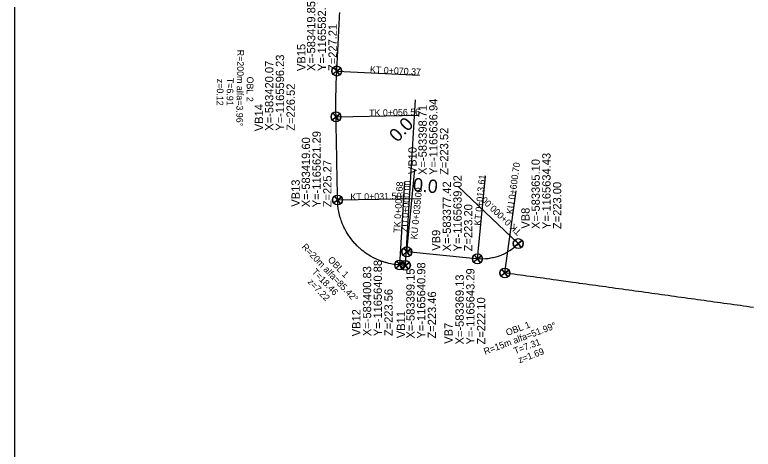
# Model space of a CAD drawing. Extents: x -583517 to -548566, y -1166112 to -1101582.
# Drawn here: x -583517 to -583294.2, y -1165696.4 to -1165565.5 of the extents above; entities that cross this region are included whole.
import ezdxf

# ---------------------------------------------------------------- set-up
doc = ezdxf.new("R2010")
doc.units = 0
for name, color, linetype in [('13', 7, 'Continuous'), ('56', 7, 'Continuous'), ('59', 7, 'Continuous'), ('8', 7, 'Continuous'), ('Body pricny rez', 7, 'Continuous'), ('Popis pricneho profilu', 7, 'Continuous')]:
    doc.layers.add(name, color=color, linetype=linetype)

msp = doc.modelspace()

# ---------------------------------------------------------------- linework, layer by layer
at = {"layer": '13'}
for points in [[(-583419.85, -1165582.42), (-583394.88, -1165583.68)], [(-583399.15, -1165640.98), (-583396.09, -1165591.07)], [(-583420.07, -1165596.23), (-583395.07, -1165595.77)], [(-583398.71, -1165636.94), (-583396.28, -1165612.06)], [(-583377.42, -1165639.02), (-583374.99, -1165614.13)], [(-583400.83, -1165640.88), (-583399.3, -1165615.92)], [(-583399.15, -1165640.98), (-583397.62, -1165616.03)], [(-583365.1, -1165634.43), (-583383.21, -1165617.19)], [(-583369.13, -1165643.29), (-583365.69, -1165618.53)], [(-583419.6, -1165621.29), (-583394.6, -1165620.82)]]:
    msp.add_lwpolyline(points, dxfattribs=at)
at = {"layer": '56'}
msp.add_lwpolyline([(-583365.1, -1165634.43), (-583365.66, -1165634.99), (-583365.81, -1165635.13), (-583366.26, -1165635.53), (-583366.57, -1165635.78), (-583366.88, -1165636.03), (-583367.37, -1165636.38), (-583367.53, -1165636.5), (-583368.21, -1165636.93), (-583368.21, -1165636.93), (-583368.9, -1165637.32), (-583369.08, -1165637.41), (-583369.62, -1165637.68), (-583369.98, -1165637.84), (-583370.36, -1165638), (-583370.91, -1165638.21), (-583371.11, -1165638.28), (-583371.86, -1165638.52), (-583371.87, -1165638.52), (-583372.65, -1165638.72), (-583372.83, -1165638.76), (-583373.43, -1165638.87), (-583373.82, -1165638.93), (-583374.22, -1165638.99), (-583374.81, -1165639.04), (-583375.02, -1165639.06), (-583375.81, -1165639.09), (-583375.82, -1165639.09), (-583376.62, -1165639.07), (-583376.81, -1165639.06), (-583377.42, -1165639.02), (-583377.81, -1165638.98), (-583378.8, -1165638.88), (-583379.8, -1165638.78), (-583380.79, -1165638.69), (-583381.79, -1165638.59), (-583382.78, -1165638.49), (-583383.78, -1165638.4), (-583384.77, -1165638.3), (-583385.77, -1165638.2), (-583386.76, -1165638.1), (-583387.76, -1165638.01), (-583388.75, -1165637.91), (-583389.75, -1165637.81), (-583390.74, -1165637.72), (-583391.74, -1165637.62), (-583392.74, -1165637.52), (-583393.73, -1165637.42), (-583394.73, -1165637.33), (-583395.72, -1165637.23), (-583396.72, -1165637.13), (-583397.71, -1165637.04), (-583398.71, -1165636.94)], dxfattribs=at)
at = {"layer": '8'}
for p, q in [((-583421.05, -1165583.31), (-583418.64, -1165581.52)), ((-583419.85, -1165582.42), (-583420.74, -1165581.21)), ((-583418.95, -1165583.62), (-583420.74, -1165581.22)), ((-583418.64, -1165581.52), (-583419.85, -1165582.42)), ((-583418.64, -1165581.52), (-583419.85, -1165582.42)), ((-583421.05, -1165583.31), (-583419.85, -1165582.42)), ((-583419.85, -1165582.42), (-583418.95, -1165583.62)), ((-583419.85, -1165582.42), (-583418.95, -1165583.62)), ((-583419.17, -1165597.43), (-583420.96, -1165595.03)), ((-583420.07, -1165596.23), (-583420.96, -1165595.03)), ((-583421.27, -1165597.13), (-583418.86, -1165595.34)), ((-583421.27, -1165597.13), (-583420.07, -1165596.23)), ((-583418.86, -1165595.34), (-583420.07, -1165596.23)), ((-583418.86, -1165595.34), (-583420.07, -1165596.23)), ((-583420.07, -1165596.23), (-583419.17, -1165597.44)), ((-583420.07, -1165596.23), (-583419.17, -1165597.44)), ((-583420.8, -1165622.18), (-583418.4, -1165620.39)), ((-583420.8, -1165622.18), (-583419.6, -1165621.29)), ((-583419.6, -1165621.29), (-583420.5, -1165620.08)), ((-583418.71, -1165622.49), (-583420.49, -1165620.08)), ((-583418.4, -1165620.39), (-583419.6, -1165621.29)), ((-583418.4, -1165620.39), (-583419.6, -1165621.29)), ((-583419.6, -1165621.29), (-583418.7, -1165622.49)), ((-583419.6, -1165621.29), (-583418.7, -1165622.49)), ((-583366.3, -1165635.32), (-583363.89, -1165633.53)), ((-583366.3, -1165635.32), (-583365.1, -1165634.43)), ((-583364.2, -1165635.63), (-583365.99, -1165633.22)), ((-583365.1, -1165634.43), (-583365.99, -1165633.22)), ((-583363.89, -1165633.53), (-583365.1, -1165634.43)), ((-583363.89, -1165633.53), (-583365.1, -1165634.43)), ((-583365.1, -1165634.43), (-583364.2, -1165635.63)), ((-583365.1, -1165634.43), (-583364.2, -1165635.63)), ((-583399.91, -1165637.83), (-583397.5, -1165636.04)), ((-583399.91, -1165637.83), (-583398.71, -1165636.94)), ((-583397.81, -1165638.14), (-583399.6, -1165635.73)), ((-583398.71, -1165636.94), (-583399.6, -1165635.73)), ((-583397.5, -1165636.04), (-583398.71, -1165636.94)), ((-583397.5, -1165636.04), (-583398.71, -1165636.94)), ((-583398.71, -1165636.94), (-583397.81, -1165638.14)), ((-583398.71, -1165636.94), (-583397.81, -1165638.14)), ((-583378.62, -1165639.91), (-583376.22, -1165638.12)), ((-583378.62, -1165639.91), (-583377.42, -1165639.02)), ((-583376.52, -1165640.22), (-583378.31, -1165637.81)), ((-583377.42, -1165639.02), (-583378.31, -1165637.81)), ((-583376.21, -1165638.12), (-583377.42, -1165639.02)), ((-583376.21, -1165638.12), (-583377.42, -1165639.02)), ((-583377.42, -1165639.02), (-583376.52, -1165640.22)), ((-583377.42, -1165639.02), (-583376.52, -1165640.22)), ((-583402.03, -1165641.77), (-583399.62, -1165639.98)), ((-583402.03, -1165641.77), (-583400.83, -1165640.88)), ((-583399.93, -1165642.08), (-583401.72, -1165639.67)), ((-583400.83, -1165640.88), (-583401.72, -1165639.67)), ((-583399.62, -1165639.98), (-583400.83, -1165640.88)), ((-583399.62, -1165639.98), (-583400.83, -1165640.88)), ((-583400.83, -1165640.88), (-583399.93, -1165642.08)), ((-583400.83, -1165640.88), (-583399.93, -1165642.08)), ((-583400.36, -1165641.88), (-583397.95, -1165640.09)), ((-583400.36, -1165641.88), (-583399.15, -1165640.98)), ((-583398.26, -1165642.18), (-583400.05, -1165639.78)), ((-583399.15, -1165640.98), (-583400.05, -1165639.78)), ((-583397.95, -1165640.09), (-583399.15, -1165640.98)), ((-583397.95, -1165640.09), (-583399.15, -1165640.98)), ((-583399.15, -1165640.98), (-583398.26, -1165642.18)), ((-583399.15, -1165640.98), (-583398.26, -1165642.18)), ((-583370.33, -1165644.19), (-583367.92, -1165642.4)), ((-583370.33, -1165644.19), (-583369.13, -1165643.29)), ((-583368.23, -1165644.5), (-583370.02, -1165642.09)), ((-583369.13, -1165643.29), (-583370.02, -1165642.09)), ((-583367.92, -1165642.4), (-583369.13, -1165643.29)), ((-583367.92, -1165642.4), (-583369.13, -1165643.29)), ((-583369.13, -1165643.29), (-583368.23, -1165644.5)), ((-583369.13, -1165643.29), (-583368.23, -1165644.5))]:
    msp.add_line(p, q, dxfattribs=at)
for centre in [(-583419.85, -1165582.42), (-583420.07, -1165596.23), (-583419.6, -1165621.29), (-583365.1, -1165634.43), (-583398.71, -1165636.94), (-583400.83, -1165640.88), (-583399.15, -1165640.98), (-583377.42, -1165639.02), (-583369.13, -1165643.29)]:
    msp.add_circle(centre, 1.5, dxfattribs=at)
for centre, start, end in [((-583419.85, -1165582.42), 126.6271, 216.6271), ((-583419.85, -1165582.42), 306.6271, 36.6271), ((-583419.85, -1165582.42), 306.6271, 36.6271), ((-583420.07, -1165596.23), 126.6271, 216.6271), ((-583420.07, -1165596.23), 306.6271, 36.6271), ((-583420.07, -1165596.23), 306.6271, 36.6271), ((-583419.6, -1165621.29), 126.6271, 216.6271), ((-583419.6, -1165621.29), 306.6271, 36.6271), ((-583419.6, -1165621.29), 306.6271, 36.6271), ((-583365.1, -1165634.43), 126.6271, 216.6271), ((-583365.1, -1165634.43), 306.6271, 36.6271), ((-583365.1, -1165634.43), 306.6271, 36.6271), ((-583398.71, -1165636.94), 126.6271, 216.6271), ((-583398.71, -1165636.94), 306.6271, 36.6271), ((-583398.71, -1165636.94), 306.6271, 36.6271), ((-583377.42, -1165639.02), 126.6271, 216.6271), ((-583377.42, -1165639.02), 306.6271, 36.6271), ((-583377.42, -1165639.02), 306.6271, 36.6271), ((-583400.83, -1165640.88), 126.6271, 216.6271), ((-583399.15, -1165640.98), 126.6271, 216.6271), ((-583400.83, -1165640.88), 306.6271, 36.6271), ((-583400.83, -1165640.88), 306.6271, 36.6271), ((-583399.15, -1165640.98), 306.6271, 36.6271), ((-583399.15, -1165640.98), 306.6271, 36.6271), ((-583369.13, -1165643.29), 126.6271, 216.6271), ((-583369.13, -1165643.29), 306.6271, 36.6271), ((-583369.13, -1165643.29), 306.6271, 36.6271)]:
    msp.add_arc(centre, 1.5, start, end, dxfattribs=at)
at = {"layer": 'Body pricny rez'}
for points in [[(-583399.15, -1165640.98), (-583400.15, -1165640.92), (-583400.83, -1165640.88), (-583401.15, -1165640.86), (-583401.73, -1165640.8), (-583402.14, -1165640.75), (-583402.62, -1165640.69), (-583403.13, -1165640.6), (-583403.51, -1165640.53), (-583404.11, -1165640.4), (-583404.4, -1165640.33), (-583405.08, -1165640.15), (-583405.27, -1165640.1), (-583406.03, -1165639.85), (-583406.13, -1165639.82), (-583406.97, -1165639.51), (-583406.97, -1165639.51), (-583406.98, -1165639.51), (-583407.81, -1165639.15), (-583407.89, -1165639.12), (-583408.62, -1165638.77), (-583408.79, -1165638.68), (-583409.42, -1165638.34), (-583409.67, -1165638.2), (-583410.2, -1165637.88), (-583410.52, -1165637.67), (-583410.95, -1165637.38), (-583411.34, -1165637.11), (-583411.68, -1165636.85), (-583412.14, -1165636.5), (-583412.39, -1165636.29), (-583412.9, -1165635.85), (-583413.07, -1165635.7), (-583413.63, -1165635.17), (-583413.73, -1165635.08), (-583414.33, -1165634.45), (-583414.35, -1165634.42), (-583414.95, -1165633.74), (-583414.98, -1165633.7), (-583415.51, -1165633.04), (-583415.6, -1165632.91), (-583416.04, -1165632.31), (-583416.18, -1165632.1), (-583416.54, -1165631.55), (-583416.72, -1165631.26), (-583417, -1165630.78), (-583417.22, -1165630.39), (-583417.43, -1165629.98), (-583417.67, -1165629.5), (-583417.82, -1165629.17), (-583418.08, -1165628.58), (-583418.18, -1165628.33), (-583418.44, -1165627.65), (-583418.49, -1165627.49), (-583418.75, -1165626.7), (-583418.77, -1165626.63), (-583419.01, -1165625.76), (-583419.01, -1165625.74), (-583419.21, -1165624.88), (-583419.23, -1165624.76), (-583419.37, -1165623.99), (-583419.4, -1165623.77), (-583419.48, -1165623.09), (-583419.52, -1165622.78), (-583419.56, -1165622.19), (-583419.58, -1165621.78), (-583419.6, -1165621.29), (-583419.61, -1165620.78), (-583419.63, -1165619.78), (-583419.65, -1165618.78), (-583419.67, -1165617.78), (-583419.68, -1165616.78), (-583419.7, -1165615.78), (-583419.72, -1165614.78), (-583419.74, -1165613.78), (-583419.76, -1165612.79), (-583419.78, -1165611.79), (-583419.8, -1165610.79), (-583419.81, -1165609.79), (-583419.83, -1165608.79), (-583419.85, -1165607.79), (-583419.87, -1165606.79), (-583419.89, -1165605.79), (-583419.91, -1165604.79), (-583419.93, -1165603.79), (-583419.94, -1165602.79), (-583419.96, -1165601.79), (-583419.98, -1165600.79), (-583420, -1165599.79), (-583420.02, -1165598.79), (-583420.04, -1165597.79), (-583420.06, -1165596.79), (-583420.07, -1165596.23), (-583420.07, -1165595.79), (-583420.09, -1165594.79), (-583420.1, -1165593.79), (-583420.1, -1165592.79), (-583420.1, -1165592.78), (-583420.1, -1165591.79), (-583420.09, -1165590.79), (-583420.08, -1165589.79), (-583420.08, -1165589.32), (-583420.07, -1165588.79), (-583420.05, -1165587.79), (-583420.02, -1165586.79), (-583419.99, -1165585.87), (-583419.99, -1165585.79), (-583419.95, -1165584.79), (-583419.91, -1165583.79), (-583419.87, -1165582.79), (-583419.85, -1165582.42), (-583419.82, -1165581.79), (-583419.76, -1165580.79), (-583419.71, -1165579.8), (-583419.66, -1165578.8), (-583419.61, -1165577.8), (-583419.56, -1165576.8), (-583419.51, -1165575.8), (-583419.46, -1165574.8), (-583419.41, -1165573.8), (-583419.36, -1165572.8), (-583419.31, -1165571.81), (-583419.26, -1165570.81), (-583419.21, -1165569.81), (-583419.16, -1165568.81), (-583419.11, -1165567.81), (-583419.06, -1165566.81), (-583419.01, -1165565.81), (-583418.96, -1165564.81)], [(-583294.14, -1165653.69), (-583295.13, -1165653.55), (-583296.12, -1165653.42), (-583297.11, -1165653.28), (-583298.1, -1165653.14), (-583299.1, -1165653.01), (-583300.09, -1165652.87), (-583301.08, -1165652.73), (-583302.07, -1165652.59), (-583303.06, -1165652.46), (-583304.05, -1165652.32), (-583305.04, -1165652.18), (-583306.03, -1165652.04), (-583307.02, -1165651.91), (-583308.01, -1165651.77), (-583309, -1165651.63), (-583309.99, -1165651.49), (-583310.98, -1165651.36), (-583311.97, -1165651.22), (-583312.96, -1165651.08), (-583313.95, -1165650.94), (-583314.94, -1165650.81), (-583315.93, -1165650.67), (-583316.92, -1165650.53), (-583317.92, -1165650.4), (-583318.91, -1165650.26), (-583319.9, -1165650.12), (-583320.89, -1165649.98), (-583321.88, -1165649.85), (-583322.87, -1165649.71), (-583323.86, -1165649.57), (-583324.85, -1165649.43), (-583325.84, -1165649.3), (-583326.83, -1165649.16), (-583327.82, -1165649.02), (-583328.81, -1165648.88), (-583329.8, -1165648.75), (-583330.79, -1165648.61), (-583331.78, -1165648.47), (-583332.77, -1165648.34), (-583333.76, -1165648.2), (-583334.75, -1165648.06), (-583335.74, -1165647.92), (-583336.74, -1165647.79), (-583337.73, -1165647.65), (-583338.72, -1165647.51), (-583339.71, -1165647.37), (-583340.7, -1165647.24), (-583341.69, -1165647.1), (-583342.68, -1165646.96), (-583343.67, -1165646.82), (-583344.66, -1165646.69), (-583345.65, -1165646.55), (-583346.64, -1165646.41), (-583346.88, -1165646.38), (-583347.63, -1165646.27), (-583348.62, -1165646.14), (-583353.57, -1165645.45), (-583354.56, -1165645.31), (-583355.56, -1165645.18), (-583356.55, -1165645.04), (-583357.54, -1165644.9), (-583358.53, -1165644.76), (-583359.52, -1165644.63), (-583360.51, -1165644.49), (-583361.5, -1165644.35), (-583362.49, -1165644.21), (-583363.48, -1165644.08), (-583364.47, -1165643.94), (-583365.46, -1165643.8), (-583366.45, -1165643.66), (-583367.44, -1165643.53), (-583368.43, -1165643.39), (-583369.13, -1165643.29)]]:
    msp.add_lwpolyline(points, dxfattribs=at)
at = {"layer": 'Popis pricneho profilu'}
msp.add_lwpolyline([(-583516.97, -1166111.82), (-583516.97, -1165166.82), (-583071.47, -1165166.82), (-583071.47, -1166111.82)], close=True, dxfattribs=at)

# ---------------------------------------------------------------- texts
at = {"layer": '13'}
for s, height, rotation, p in [('R=200m alfa=3.96%%d', 2, 269.0882, (-583449.81, -1165575.97)), ('KT 0+070.37', 2, 357.1091, (-583409.86, -1165582.92)), ('   z=0.12', 2, 269.0882, (-583455.92, -1165582.51)), ('  T=6.91', 2, 269.0882, (-583452.93, -1165582.97)), ('OBL 2', 2, 269.0882, (-583446.94, -1165584.09)), ('TK 0+056.56', 2, 1.0672, (-583410.07, -1165596.04)), ('0.0', 4, 46.4159, (-583401.55, -1165604.1)), ('KU 0+600.70', 2, 82.1049, (-583366.69, -1165625.64)), ('0.0', 4, 354.4257, (-583396.99, -1165618.56)), ('KT 0+013.61', 2, 84.4257, (-583376.45, -1165629.06)), ('TK 0+001.68', 2, 86.4886, (-583400.75, -1165631.18)), ('ZU 0+000.00', 2, 86.4886, (-583398.54, -1165631)), ('KT 0+031.50', 2, 1.0672, (-583415.72, -1165621.35)), ('KU 0+035.00', 2, 84.4257, (-583395.59, -1165633.22)), ('TK 0+000.00', 2, 136.4159, (-583363.97, -1165630.72)), ('R=20m alfa=85.42%%d', 2, 313.7779, (-583430.57, -1165635.57)), ('OBL 1', 2, 313.7779, (-583422.69, -1165639.45)), ('  T=18.46', 2, 313.7779, (-583428.53, -1165642.03)), ('   z=7.22', 2, 313.7779, (-583430.31, -1165644.51)), ('R=15m alfa=51.99%%d', 2, 20.4208, (-583375.09, -1165667.97)), ('OBL 1', 2, 20.4208, (-583368.4, -1165662.28)), ('  T=7.31', 2, 20.4208, (-583367.44, -1165668.32)), ('   z=1.69', 2, 20.4208, (-583366.79, -1165671.28))]:
    msp.add_text(s, height=height, rotation=rotation, dxfattribs=at).set_placement(p)
at = {"layer": '59'}
for s, p in [('X=-583419.85', (-583426.32, -1165582.42)), ('Y=-1165582.42', (-583423.08, -1165582.42)), ('Z=227.21', (-583419.85, -1165582.42)), ('VB15', (-583429.3, -1165582.42)), ('Y=-1165596.23', (-583435.73, -1165600.42)), ('X=-583420.07', (-583438.97, -1165600.42)), ('Z=226.52', (-583432.5, -1165600.42)), ('VB14', (-583442.07, -1165600.57)), ('X=-583398.71', (-583392.7, -1165613.72)), ('Y=-1165636.94', (-583389.47, -1165613.72)), ('Y=-1165621.29', (-583424.68, -1165623.48)), ('Z=223.52', (-583386.23, -1165613.72)), ('X=-583419.60', (-583427.91, -1165623.48)), ('VB10', (-583395.76, -1165613.49)), ('Y=-1165634.43', (-583355.36, -1165630.05)), ('Z=225.27', (-583421.44, -1165623.48)), ('X=-583365.10', (-583358.6, -1165630.05)), ('Y=-1165639.02', (-583382.17, -1165636.77)), ('VB13', (-583431.01, -1165623.32)), ('X=-583377.42', (-583385.4, -1165636.77)), ('Z=223.00', (-583352.13, -1165630.05)), ('Z=223.20', (-583378.93, -1165636.77)), ('VB8', (-583361.69, -1165629.93)), ('VB9', (-583388.64, -1165636.59)), ('Y=-1165640.88', (-583406.23, -1165662.32)), ('X=-583400.83', (-583409.46, -1165662.32)), ('Y=-1165640.98', (-583393.12, -1165663.05)), ('X=-583399.15', (-583396.36, -1165663.05)), ('X=-583369.13', (-583381.54, -1165664.84)), ('Y=-1165643.29', (-583378.3, -1165664.84)), ('Z=223.56', (-583402.99, -1165662.32)), ('Z=223.46', (-583389.89, -1165663.05)), ('Z=222.10', (-583375.06, -1165664.84)), ('VB12', (-583412.7, -1165662.37)), ('VB11', (-583399.23, -1165662.94)), ('VB7', (-583384.89, -1165664.63))]:
    msp.add_text(s, height=2.5, rotation=90, dxfattribs=at).set_placement(p)

doc.saveas('drawing.dxf')
